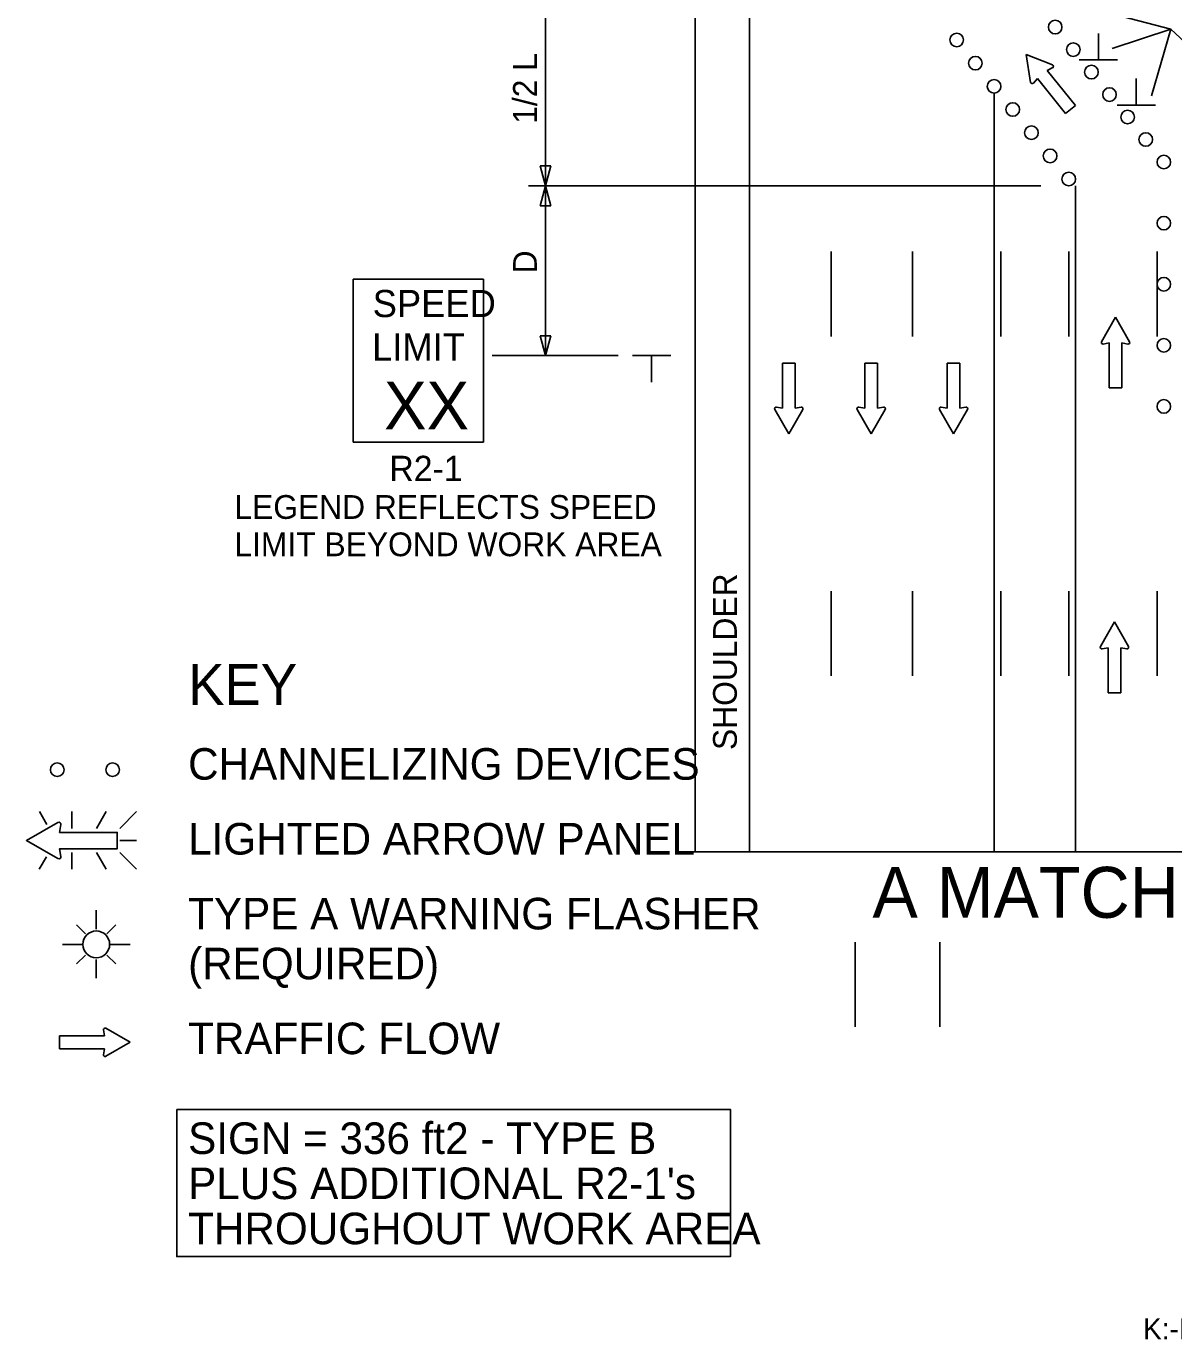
# Model space of a CAD drawing. Extents: x 16038 to 19504, y 5710 to 8321.
# Drawn here: x 16741.7 to 17079.6, y 5931.8 to 6320.5 of the extents above; entities that cross this region are included whole.
import ezdxf

# ---------------------------------------------------------------- set-up
doc = ezdxf.new("R2010")
doc.units = 0
for name, color, linetype in [('ALI_LEGAL_EX', 7, 'Continuous'), ('BORDER_SIGNAL_WO', 7, 'Continuous'), ('MT_SCRATCH_LEVEL_E', 7, 'Continuous'), ('PAVT_EDGE_EX', 7, 'Continuous'), ('TRAFFIC_SIGNS_PR', 7, 'Continuous'), ('TYPICAL_EX', 7, 'Continuous'), ('TYPICAL_TEXT_DIMEN_EX', 7, 'Continuous'), ('TYPICAL_TEXT_DIMEN_PR', 7, 'Continuous')]:
    doc.layers.add(name, color=color, linetype=linetype)

msp = doc.modelspace()

# ---------------------------------------------------------------- linework, layer by layer
at = {"layer": 'ALI_LEGAL_EX'}
for points in [[(16978.71, 6229.12), (16978.71, 6254.12)], [(17002.71, 6229.12), (17002.71, 6254.12)], [(17028.71, 6229.12), (17028.71, 6254.12)], [(17048.71, 6229.12), (17048.71, 6254.12)], [(17074.71, 6229.12), (17074.71, 6254.12)], [(16978.71, 6129.12), (16978.71, 6154.12)], [(17002.71, 6129.12), (17002.71, 6154.12)], [(17028.71, 6129.12), (17028.71, 6154.12)], [(17048.71, 6129.12), (17048.71, 6154.12)], [(17074.71, 6129.12), (17074.71, 6154.12)]]:
    msp.add_lwpolyline(points, dxfattribs=at)
at = {"layer": 'MT_SCRATCH_LEVEL_E'}
for p, q in [((17036.14, 6312.18), (17037.48, 6303.97)), ((17043.92, 6309.15), (17036.14, 6312.18)), ((17036.14, 6312.18), (17037.48, 6303.97)), ((17043.92, 6309.15), (17036.14, 6312.18)), ((17042.39, 6307.44), (17043.97, 6308.31)), ((17042.39, 6307.44), (17043.97, 6308.31)), ((17038.29, 6303.74), (17039.47, 6305.1)), ((17038.29, 6303.74), (17039.47, 6305.1)), ((17039.47, 6305.1), (17047.79, 6294.77)), ((17039.47, 6305.1), (17047.79, 6294.77)), ((17050.7, 6297.12), (17042.39, 6307.44)), ((17050.7, 6297.12), (17042.39, 6307.44)), ((17047.79, 6294.77), (17050.7, 6297.12)), ((17047.79, 6294.77), (17050.7, 6297.12)), ((17062.47, 6234.81), (17058.36, 6227.57)), ((17062.47, 6234.81), (17058.36, 6227.57)), ((17066.62, 6227.57), (17062.47, 6234.81)), ((17066.62, 6227.57), (17062.47, 6234.81)), ((17058.85, 6226.89), (17060.62, 6227.2)), ((17058.85, 6226.89), (17060.62, 6227.2)), ((17060.62, 6227.2), (17060.62, 6213.95)), ((17060.62, 6227.2), (17060.62, 6213.95)), ((17064.36, 6213.95), (17064.36, 6227.2)), ((17064.36, 6227.2), (17066.14, 6226.89)), ((17064.36, 6213.95), (17064.36, 6227.2)), ((17064.36, 6227.2), (17066.14, 6226.89)), ((16968.12, 6221.27), (16964.38, 6221.27)), ((16964.38, 6221.27), (16964.38, 6208.02)), ((16968.12, 6221.27), (16964.38, 6221.27)), ((16964.38, 6221.27), (16964.38, 6208.02)), ((16968.12, 6208.02), (16968.12, 6221.27)), ((16968.12, 6208.02), (16968.12, 6221.27)), ((16992.38, 6221.27), (16988.64, 6221.27)), ((16988.64, 6221.27), (16988.64, 6208.02)), ((16992.38, 6221.27), (16988.64, 6221.27)), ((16988.64, 6221.27), (16988.64, 6208.02)), ((16992.38, 6208.02), (16992.38, 6221.27)), ((16992.38, 6208.02), (16992.38, 6221.27)), ((17016.64, 6221.27), (17012.89, 6221.27)), ((17012.89, 6221.27), (17012.89, 6208.02)), ((17016.64, 6221.27), (17012.89, 6221.27)), ((17012.89, 6221.27), (17012.89, 6208.02)), ((17016.64, 6208.02), (17016.64, 6221.27)), ((17016.64, 6208.02), (17016.64, 6221.27)), ((17060.62, 6213.95), (17064.36, 6213.95)), ((17060.62, 6213.95), (17064.36, 6213.95)), ((16962.12, 6207.65), (16966.27, 6200.41)), ((16962.12, 6207.65), (16966.27, 6200.41)), ((16964.38, 6208.02), (16962.6, 6208.33)), ((16964.38, 6208.02), (16962.6, 6208.33)), ((16966.27, 6200.41), (16970.38, 6207.65)), ((16966.27, 6200.41), (16970.38, 6207.65)), ((16969.9, 6208.33), (16968.12, 6208.02)), ((16969.9, 6208.33), (16968.12, 6208.02)), ((16986.38, 6207.65), (16990.53, 6200.41)), ((16986.38, 6207.65), (16990.53, 6200.41)), ((16988.64, 6208.02), (16986.86, 6208.33)), ((16988.64, 6208.02), (16986.86, 6208.33)), ((16990.53, 6200.41), (16994.64, 6207.65)), ((16990.53, 6200.41), (16994.64, 6207.65)), ((16994.16, 6208.33), (16992.38, 6208.02)), ((16994.16, 6208.33), (16992.38, 6208.02)), ((17010.64, 6207.65), (17014.78, 6200.41)), ((17010.64, 6207.65), (17014.78, 6200.41)), ((17012.89, 6208.02), (17011.12, 6208.33)), ((17012.89, 6208.02), (17011.12, 6208.33)), ((17014.78, 6200.41), (17018.89, 6207.65)), ((17014.78, 6200.41), (17018.89, 6207.65)), ((17018.41, 6208.33), (17016.64, 6208.02)), ((17018.41, 6208.33), (17016.64, 6208.02)), ((17062.15, 6145.03), (17058.03, 6137.79)), ((17062.15, 6145.03), (17058.03, 6137.79)), ((17066.29, 6137.79), (17062.15, 6145.03)), ((17066.29, 6137.79), (17062.15, 6145.03)), ((17058.52, 6137.11), (17060.29, 6137.42)), ((17058.52, 6137.11), (17060.29, 6137.42)), ((17060.29, 6137.42), (17060.29, 6124.16)), ((17060.29, 6137.42), (17060.29, 6124.16)), ((17064.04, 6124.16), (17064.04, 6137.42)), ((17064.04, 6137.42), (17065.81, 6137.11)), ((17064.04, 6124.16), (17064.04, 6137.42)), ((17064.04, 6137.42), (17065.81, 6137.11)), ((17060.29, 6124.16), (17064.04, 6124.16)), ((17060.29, 6124.16), (17064.04, 6124.16)), ((16764.4, 6024.83), (16764.71, 6023.05)), ((16764.4, 6024.83), (16764.71, 6023.05)), ((16772.32, 6021.2), (16765.08, 6025.31)), ((16772.32, 6021.2), (16765.08, 6025.31)), ((16764.71, 6023.05), (16751.45, 6023.05)), ((16751.45, 6023.05), (16751.45, 6019.31)), ((16764.71, 6023.05), (16751.45, 6023.05)), ((16751.45, 6023.05), (16751.45, 6019.31)), ((16765.08, 6017.06), (16772.32, 6021.2)), ((16765.08, 6017.06), (16772.32, 6021.2)), ((16751.45, 6019.31), (16764.71, 6019.31)), ((16751.45, 6019.31), (16764.71, 6019.31)), ((16764.71, 6019.31), (16764.4, 6017.53)), ((16764.71, 6019.31), (16764.4, 6017.53))]:
    msp.add_line(p, q, dxfattribs=at)
for centre, start, end in [((17043.74, 6308.71), 298.877, 68.6139), ((17043.74, 6308.71), 298.877, 68.6139), ((17037.94, 6304.05), 189.2656, 318.8046), ((17037.94, 6304.05), 189.2656, 318.8046), ((17058.77, 6227.35), 150.4248, 279.9638), ((17058.77, 6227.35), 150.4248, 279.9638), ((17066.21, 6227.35), 260.0362, 29.7731), ((17066.21, 6227.35), 260.0362, 29.7731), ((16962.53, 6207.87), 80.0362, 209.7731), ((16962.53, 6207.87), 80.0362, 209.7731), ((16969.97, 6207.87), 330.4248, 99.9638), ((16969.97, 6207.87), 330.4248, 99.9638), ((16986.79, 6207.87), 80.0362, 209.7731), ((16986.79, 6207.87), 80.0362, 209.7731), ((16994.23, 6207.87), 330.4248, 99.9638), ((16994.23, 6207.87), 330.4248, 99.9638), ((17011.05, 6207.87), 80.0362, 209.7731), ((17011.05, 6207.87), 80.0362, 209.7731), ((17018.49, 6207.87), 330.4248, 99.9638), ((17018.49, 6207.87), 330.4248, 99.9638), ((17058.44, 6137.56), 150.4248, 279.9638), ((17058.44, 6137.56), 150.4248, 279.9638), ((17065.88, 6137.57), 260.0362, 29.7731), ((17065.88, 6137.57), 260.0362, 29.7731), ((16764.85, 6024.91), 60.4248, 189.9638), ((16764.85, 6024.91), 60.4248, 189.9638), ((16764.86, 6017.46), 170.0362, 299.7731), ((16764.86, 6017.46), 170.0362, 299.7731)]:
    msp.add_arc(centre, 0.463, start, end, dxfattribs=at)
at = {"layer": 'PAVT_EDGE_EX'}
for p, q in [((16954.71, 6925.32), (16954.71, 6077.44)), ((16938.71, 6780.67), (16938.71, 6077.44)), ((17026.71, 6300.81), (17026.71, 6077.44)), ((17050.71, 6273.49), (17050.71, 6077.44))]:
    msp.add_line(p, q, dxfattribs=at)
for points in [[(16985.78, 6025.74), (16985.78, 6050.74)], [(16985.78, 6025.74), (16985.78, 6050.74)], [(17010.78, 6025.74), (17010.78, 6050.74)], [(17010.78, 6025.74), (17010.78, 6050.74)]]:
    msp.add_lwpolyline(points, dxfattribs=at)
at = {"layer": 'TRAFFIC_SIGNS_PR'}
for p, q in [((16837.95, 6245.97), (16876.35, 6245.97)), ((16837.95, 6197.97), (16837.95, 6245.97)), ((16876.35, 6197.97), (16876.35, 6245.97)), ((16837.95, 6197.97), (16876.35, 6197.97)), ((16747.76, 6085.32), (16745.56, 6089.14)), ((16755.08, 6084.21), (16755.08, 6089.14)), ((16762.32, 6084.21), (16765.17, 6089.14)), ((16769.23, 6084.21), (16774.17, 6089.15)), ((16769.23, 6080.65), (16774.17, 6080.65)), ((16745.51, 6072.16), (16747.63, 6075.82)), ((16755.08, 6077.1), (16755.08, 6072.16)), ((16765.21, 6072.16), (16762.37, 6077.1)), ((16769.23, 6077.1), (16774.17, 6072.16)), ((16762.29, 6054.49), (16762.29, 6060.11)), ((16762.29, 6054.49), (16762.29, 6060.11)), ((16759.15, 6053.19), (16756.52, 6055.82)), ((16759.15, 6053.19), (16756.52, 6055.82)), ((16765.43, 6053.19), (16768.06, 6055.82)), ((16765.43, 6053.19), (16768.06, 6055.82)), ((16758.35, 6050.05), (16752.31, 6050.05)), ((16758.35, 6050.05), (16752.31, 6050.05)), ((16766.23, 6050.05), (16772.32, 6050.05)), ((16766.23, 6050.05), (16772.32, 6050.05)), ((16759.15, 6046.91), (16756.52, 6044.28)), ((16759.15, 6046.91), (16756.52, 6044.28)), ((16762.29, 6040.11), (16762.29, 6045.61)), ((16762.29, 6040.11), (16762.29, 6045.61)), ((16765.43, 6046.91), (16768.06, 6044.28)), ((16765.43, 6046.91), (16768.06, 6044.28))]:
    msp.add_line(p, q, dxfattribs=at)
for points in [[(16751.01, 6085.93), (16741.72, 6080.65), (16751.01, 6075.33)], [(16751.89, 6075.96), (16751.49, 6078.23), (16768.5, 6078.23), (16768.5, 6083.03), (16751.49, 6083.03), (16751.89, 6085.31)]]:
    msp.add_lwpolyline(points, dxfattribs=at)
for centre, radius in [((17044.71, 6320.26), 2), ((17015.71, 6316.47), 2), ((17050.04, 6313.63), 2), ((17021.21, 6309.64), 2), ((17055.38, 6307.01), 2), ((17026.71, 6302.81), 2), ((17060.71, 6300.39), 2), ((17032.21, 6295.98), 2), ((17066.04, 6293.76), 2), ((17037.71, 6289.15), 2), ((17071.38, 6287.14), 2), ((17043.21, 6282.32), 2), ((17076.71, 6280.51), 2), ((17048.71, 6275.49), 2), ((17076.71, 6262.51), 2), ((17076.71, 6244.51), 2), ((17076.71, 6226.51), 2), ((17076.71, 6208.51), 2), ((17076.71, 6208.51), 2), ((16750.81, 6101.49), 2), ((16767.11, 6101.49), 2), ((16762.29, 6050.05), 3.94), ((16762.29, 6050.05), 3.94)]:
    msp.add_circle(centre, radius, dxfattribs=at)
for centre, radius, start, end in [((16751.3, 6085.4), 0.598, 350.7308, 118.8916), ((16751.3, 6075.86), 0.597, 241.4833, 9.9593)]:
    msp.add_arc(centre, radius, start, end, dxfattribs=at)
at = {"layer": 'TYPICAL_EX'}
msp.add_line((16938.71, 6925.32), (16938.71, 6077.44), dxfattribs=at)
at = {"layer": 'TYPICAL_TEXT_DIMEN_EX'}
msp.add_lwpolyline([(16786.01, 6001.42), (16949.04, 6001.42), (16949.04, 5958.05), (16786.01, 5958.05)], close=True, dxfattribs=at)
at = {"layer": 'TYPICAL_TEXT_DIMEN_PR'}
for p, q in [((16894.61, 6273.48), (16894.61, 6332.13)), ((17050.46, 6327.06), (17078.72, 6319.64)), ((17078.72, 6319.64), (17061.46, 6313.94)), ((17078.72, 6319.64), (17073.03, 6300.05)), ((17078.72, 6319.64), (17110.7, 6290.12)), ((17057.42, 6310.61), (17057.42, 6318.39)), ((17063.05, 6310.61), (17051.8, 6310.61)), ((17068.59, 6297.28), (17068.59, 6305.07)), ((17074.22, 6297.28), (17062.97, 6297.28)), ((16894.61, 6273.48), (16893.04, 6279.35)), ((16893.04, 6279.35), (16894.61, 6279.35)), ((16894.61, 6279.35), (16896.18, 6279.35)), ((16896.18, 6279.35), (16894.61, 6273.48)), ((16889.61, 6273.48), (17040.43, 6273.48)), ((16893.04, 6267.62), (16894.61, 6273.48)), ((16894.61, 6223.48), (16894.61, 6273.48)), ((16894.61, 6273.48), (16896.18, 6267.62)), ((16894.61, 6267.62), (16893.04, 6267.62)), ((16896.18, 6267.62), (16894.61, 6267.62)), ((16894.61, 6223.48), (16893.04, 6229.35)), ((16893.04, 6229.35), (16894.61, 6229.35)), ((16894.61, 6229.35), (16896.18, 6229.35)), ((16896.18, 6229.35), (16894.61, 6223.48)), ((16915.98, 6223.48), (16878.89, 6223.48)), ((16920.23, 6223.48), (16931.48, 6223.48)), ((16925.85, 6223.48), (16925.85, 6215.7)), ((16936.37, 6077.28), (17115.53, 6077.28))]:
    msp.add_line(p, q, dxfattribs=at)

# ---------------------------------------------------------------- texts
at = {"layer": 'BORDER_SIGNAL_WO'}
msp.add_text('K:-DGN-TSR-STDS-ENGLISH-MNTTRF-M0680a.dgn        ', height=6.2, dxfattribs=at).set_placement((17070.55, 5933.71))
at = {"layer": 'TRAFFIC_SIGNS_PR'}
for s, height, p in [('SPEED', 8, (16843.71, 6234.83)), ('LIMIT', 8, (16843.55, 6222.03)), ('XX', 14.031, (16847.06, 6201.73)), ('R2-1', 7.44, (16848.62, 6186.53))]:
    msp.add_text(s, height=height, dxfattribs=at).set_placement(p)
at = {"layer": 'TYPICAL_TEXT_DIMEN_EX'}
for s, height, p in [('KEY', 12, (16789.35, 6120.6)), ('CHANNELIZING DEVICES', 9.3, (16789.35, 6098.55)), ('LIGHTED ARROW PANEL', 9.3, (16789.35, 6076.5)), ('TYPE A WARNING FLASHER', 9.3, (16789.35, 6054.45)), ('(REQUIRED)', 9.3, (16789.35, 6039.75)), ('TRAFFIC FLOW', 9.3, (16789.35, 6017.7)), ('SIGN = 336 ft2 - TYPE B', 9.3, (16789.35, 5988.3)), ("PLUS ADDITIONAL R2-1's", 9.3, (16789.35, 5975)), ('THROUGHOUT WORK AREA', 9.3, (16789.35, 5961.7))]:
    msp.add_text(s, height=height, dxfattribs=at).set_placement(p)
at = {"layer": 'TYPICAL_TEXT_DIMEN_PR'}
for s, p in [('1/2 L', (16892.05, 6291.78)), ('D', (16892.05, 6247.7)), ('SHOULDER', (16950.95, 6107.3))]:
    msp.add_text(s, height=7, rotation=90, dxfattribs=at).set_placement(p)
for s, height, p in [('LEGEND REFLECTS SPEED', 7, (16802.98, 6175.39)), ('LIMIT BEYOND WORK AREA', 7, (16802.98, 6164.39)), ('A MATCH A', 15, (16990.88, 6057.87))]:
    msp.add_text(s, height=height, dxfattribs=at).set_placement(p)

doc.saveas('drawing.dxf')
